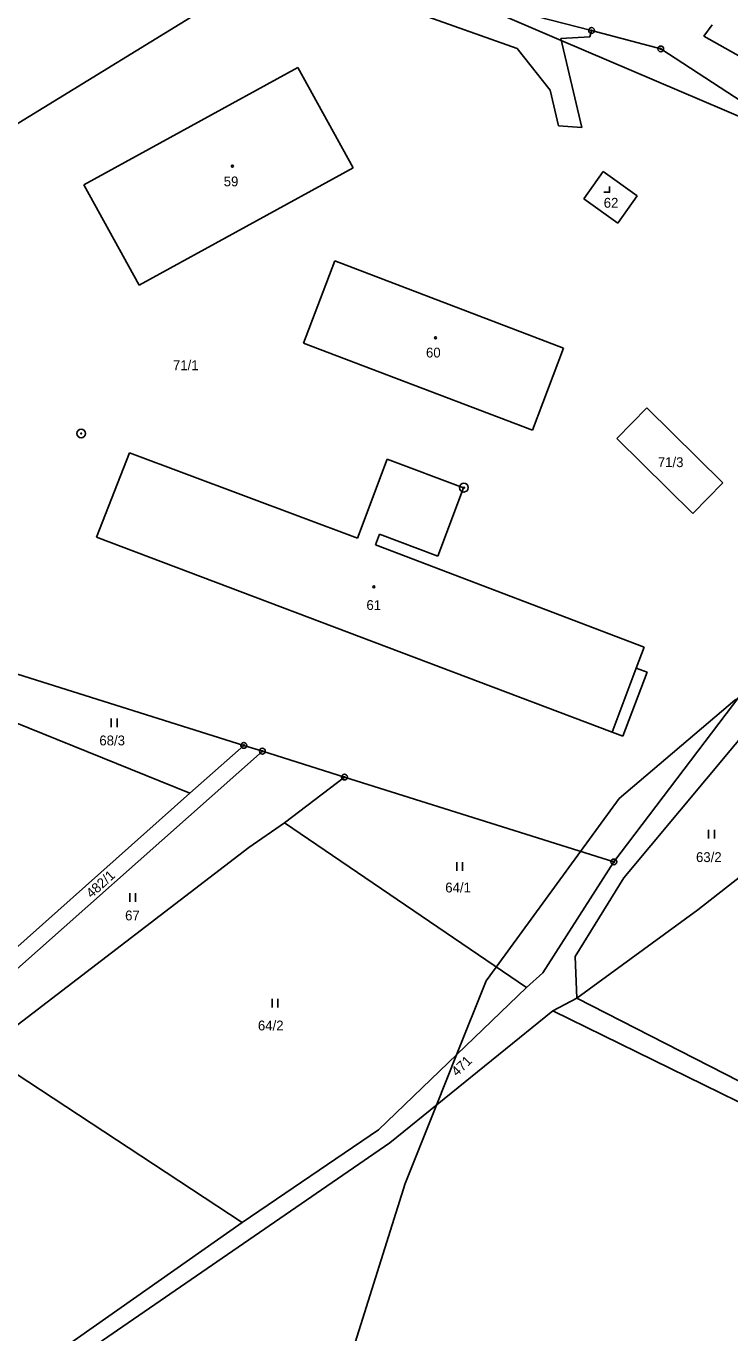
# Model space of a CAD drawing. Extents: x -547623 to -538651, y -1096714 to -1086522.
# Drawn here: x -543976.5 to -543854.9, y -1094596.8 to -1094371 of the extents above; entities that cross this region are included whole.
import ezdxf

# ---------------------------------------------------------------- set-up
doc = ezdxf.new("R2010")
doc.units = 0
for name, color, linetype in [('podzemní_provozovana', 7, 'Continuous'), ('Vrstva 1', 7, 'Continuous'), ('Vrstva 25', 7, 'Continuous'), ('Vrstva 33', 7, 'Continuous'), ('Vrstva 52', 7, 'Continuous'), ('Vrstva 83', 7, 'Continuous'), ('Vrstva 86', 7, 'Continuous'), ('Vrstva 90', 7, 'Continuous'), ('Vrstva 92', 7, 'Continuous')]:
    doc.layers.add(name, color=color, linetype=linetype)

msp = doc.modelspace()

# ---------------------------------------------------------------- linework, layer by layer
at = {"layer": 'Vrstva 1'}
for points in [[(-543930.3, -1094358.51), (-543878.77, -1094371.77)], [(-543934.68, -1094361.26), (-543986.14, -1094392.85)], [(-543911.59, -1094367.79), (-543891.65, -1094374.88)], [(-543879.1, -1094372.85), (-543878.77, -1094371.77)], [(-543878.77, -1094371.77), (-543866.82, -1094374.96)], [(-543859.39, -1094372.77), (-543857.96, -1094370.78)], [(-543829.89, -1094389.36), (-543859.39, -1094372.77)], [(-543891.65, -1094374.88), (-543885.92, -1094382.07)], [(-543884.09, -1094373.19), (-543879.1, -1094372.85)], [(-543880.43, -1094388.54), (-543884.09, -1094373.19)], [(-543866.82, -1094374.96), (-543852.74, -1094384.1)], [(-543929.5, -1094378.15), (-543966.48, -1094398.44)], [(-543919.98, -1094395.49), (-543929.5, -1094378.15)], [(-543885.92, -1094382.07), (-543884.46, -1094388.27)], [(-543884.46, -1094388.27), (-543880.43, -1094388.54)], [(-543956.96, -1094415.79), (-543919.98, -1094395.49)], [(-543876.76, -1094396.14), (-543880.13, -1094400.86)], [(-543870.87, -1094400.33), (-543876.76, -1094396.14)], [(-543966.48, -1094398.44), (-543956.96, -1094415.79)], [(-543880.13, -1094400.86), (-543874.24, -1094405.06)], [(-543870.87, -1094400.33), (-543874.24, -1094405.06)], [(-543923.11, -1094411.6), (-543928.54, -1094425.82)], [(-543883.6, -1094426.69), (-543923.11, -1094411.6)], [(-543928.54, -1094425.82), (-543888.96, -1094440.86)], [(-543888.96, -1094440.86), (-543883.6, -1094426.69)], [(-543874.4, -1094442.26), (-543869.21, -1094436.99)], [(-543869.21, -1094436.99), (-543856.08, -1094449.95)], [(-543861.26, -1094455.21), (-543874.4, -1094442.26)], [(-543964.33, -1094459.31), (-543958.59, -1094444.74)], [(-543958.59, -1094444.74), (-543919.22, -1094459.51)], [(-543914.09, -1094445.85), (-543919.22, -1094459.51)], [(-543914.09, -1094445.85), (-543900.9, -1094450.8)], [(-543900.9, -1094450.8), (-543905.32, -1094462.59)], [(-543856.08, -1094449.95), (-543861.26, -1094455.21)], [(-543875.21, -1094492.99), (-543964.33, -1094459.31)], [(-543916.13, -1094460.67), (-543915.43, -1094458.8)], [(-543869.66, -1094478.31), (-543916.13, -1094460.67)], [(-543915.43, -1094458.8), (-543905.32, -1094462.59)], [(-543871.04, -1094481.96), (-543869.66, -1094478.31)], [(-543977.99, -1094482.97), (-543938.86, -1094495.3)], [(-543873.39, -1094493.68), (-543869.17, -1094482.66)], [(-543869.17, -1094482.66), (-543871.04, -1094481.96)], [(-543874.92, -1094515.44), (-543853.17, -1094486.71)], [(-543986.26, -1094488.2), (-543948.16, -1094503.56)], [(-543873.21, -1094518.16), (-543849.31, -1094489.54)], [(-543873.39, -1094493.68), (-543875.21, -1094492.99)], [(-543935.66, -1094496.3), (-543987.34, -1094542.12)], [(-543948.16, -1094503.56), (-543938.86, -1094495.3)], [(-543938.86, -1094495.3), (-543935.66, -1094496.3)], [(-543935.66, -1094496.3), (-543921.46, -1094500.78)], [(-543931.84, -1094508.7), (-543921.46, -1094500.78)], [(-543921.46, -1094500.78), (-543874.92, -1094515.44)], [(-543989.1, -1094539.95), (-543948.16, -1094503.56)], [(-543860.39, -1094523.7), (-543837.63, -1094505.87)], [(-543938.01, -1094512.93), (-543931.84, -1094508.7)], [(-543931.84, -1094508.7), (-543890.01, -1094537.16)], [(-543983.04, -1094547.44), (-543938.01, -1094512.93)], [(-543887.17, -1094534.59), (-543874.92, -1094515.44)], [(-543881.62, -1094531.79), (-543873.21, -1094518.16)], [(-543881.31, -1094538.97), (-543860.39, -1094523.7)], [(-543881.31, -1094538.97), (-543881.62, -1094531.79)], [(-543890.01, -1094537.16), (-543887.17, -1094534.59)], [(-543915.6, -1094561.71), (-543890.01, -1094537.16)], [(-543885.48, -1094541.15), (-543881.31, -1094538.97)], [(-543837.95, -1094561.18), (-543881.31, -1094538.97)], [(-543913.61, -1094563.96), (-543885.48, -1094541.15)], [(-543885.48, -1094541.15), (-543842, -1094562.45)], [(-543939.12, -1094577.76), (-543980.55, -1094550.47)], [(-543939.12, -1094577.76), (-543915.6, -1094561.71)], [(-543982.35, -1094611.21), (-543913.61, -1094563.96)], [(-543983.7, -1094609), (-543939.12, -1094577.76)]]:
    msp.add_lwpolyline(points, dxfattribs=at)
at = {"layer": 'Vrstva 25'}
for p, q in [((-543961.77, -1094492.15), (-543961.77, -1094490.65)), ((-543960.77, -1094492.15), (-543960.77, -1094490.65)), ((-543858.55, -1094511.37), (-543858.55, -1094509.87)), ((-543857.55, -1094511.37), (-543857.55, -1094509.87)), ((-543902.07, -1094516.97), (-543902.07, -1094515.47)), ((-543901.07, -1094516.97), (-543901.07, -1094515.47)), ((-543958.55, -1094522.36), (-543958.55, -1094520.86)), ((-543957.55, -1094522.36), (-543957.55, -1094520.86)), ((-543933.97, -1094540.61), (-543933.97, -1094539.11)), ((-543932.97, -1094540.61), (-543932.97, -1094539.11))]:
    msp.add_line(p, q, dxfattribs=at)
msp.add_lwpolyline([(-543876.67, -1094399.73), (-543875.67, -1094399.73), (-543875.67, -1094398.73)], dxfattribs=at)
for centre in [(-543940.84, -1094395.22), (-543905.73, -1094424.87), (-543916.38, -1094467.92)]:
    msp.add_circle(centre, 0.175, dxfattribs=at)
at = {"layer": 'Vrstva 33'}
msp.add_lwpolyline([(-543871.04, -1094481.96), (-543875.21, -1094492.99)], dxfattribs=at)
at = {"layer": 'Vrstva 52'}
for points in [[(-543884.02, -1094373.48), (-543894.5, -1094369), (-543934.32, -1094361.04), (-543934.5, -1094361), (-543935.13, -1094360.95), (-543977.3, -1094357.3), (-543986.5, -1094356.5), (-544000.5, -1094363)], [(-543777, -1094440.5), (-543789.73, -1094425.6), (-543792.58, -1094422.26), (-543795.42, -1094418.93), (-543797.5, -1094416.5), (-543813.69, -1094406.78), (-543832.5, -1094395.5), (-543839.33, -1094392.58), (-543884.02, -1094373.48)], [(-543777, -1094440.5), (-543777.95, -1094441.08), (-543810.88, -1094461.18), (-543817.75, -1094465.37), (-543819.36, -1094466.35), (-543830.75, -1094473.31), (-543853.57, -1094487.24), (-543854, -1094487.5), (-543874, -1094504.5), (-543880.67, -1094513.63), (-543895.25, -1094533.6), (-543897, -1094536), (-543902.11, -1094548.76), (-543905.58, -1094557.45), (-543911, -1094571), (-543929.5, -1094630)]]:
    msp.add_lwpolyline(points, dxfattribs=at)
at = {"layer": 'Vrstva 83'}
for centre, radius in [((-543878.77, -1094371.77), 0.5), ((-543878.77, -1094371.77), 0.1), ((-543866.82, -1094374.96), 0.5), ((-543866.82, -1094374.96), 0.1), ((-543966.95, -1094441.42), 0.75), ((-543966.95, -1094441.42), 0.1), ((-543900.82, -1094450.77), 0.75), ((-543900.82, -1094450.77), 0.1), ((-543938.86, -1094495.3), 0.5), ((-543938.86, -1094495.3), 0.1), ((-543935.66, -1094496.3), 0.5), ((-543935.66, -1094496.3), 0.1), ((-543921.46, -1094500.78), 0.5), ((-543921.46, -1094500.78), 0.1), ((-543874.92, -1094515.44), 0.5), ((-543874.92, -1094515.44), 0.1)]:
    msp.add_circle(centre, radius, dxfattribs=at)
at = {"layer": 'Vrstva 90'}
for points in [[(-543929.5, -1094378.15), (-543966.48, -1094398.44)], [(-543919.98, -1094395.49), (-543929.5, -1094378.15)], [(-543956.96, -1094415.79), (-543919.98, -1094395.49)], [(-543966.48, -1094398.44), (-543956.96, -1094415.79)], [(-543923.11, -1094411.6), (-543928.54, -1094425.82)], [(-543883.6, -1094426.69), (-543923.11, -1094411.6)], [(-543928.54, -1094425.82), (-543888.96, -1094440.86)], [(-543888.96, -1094440.86), (-543883.6, -1094426.69)], [(-543964.33, -1094459.31), (-543958.59, -1094444.74)], [(-543958.59, -1094444.74), (-543919.22, -1094459.51)], [(-543914.09, -1094445.85), (-543919.22, -1094459.51)], [(-543914.09, -1094445.85), (-543900.9, -1094450.8)], [(-543900.9, -1094450.8), (-543905.32, -1094462.59)], [(-543875.21, -1094492.99), (-543964.33, -1094459.31)], [(-543916.13, -1094460.67), (-543915.43, -1094458.8)], [(-543869.66, -1094478.31), (-543916.13, -1094460.67)], [(-543915.43, -1094458.8), (-543905.32, -1094462.59)], [(-543871.04, -1094481.96), (-543869.66, -1094478.31)], [(-543871.04, -1094481.96), (-543875.21, -1094492.99)]]:
    msp.add_lwpolyline(points, dxfattribs=at)

# ---------------------------------------------------------------- texts
at = {"layer": 'podzemní_provozovana'}
msp.add_text('471', height=1.7, rotation=43.886, dxfattribs=at).set_placement((-543902.02, -1094552.61))
at = {"layer": 'Vrstva 86'}
for s, p in [('71/1', (-543951.11, -1094430.47)), ('71/3', (-543867.32, -1094447.22)), ('68/3', (-543963.82, -1094495.3)), ('63/2', (-543860.72, -1094515.46)), ('64/1', (-543904.05, -1094520.71)), ('67', (-543959.37, -1094525.54)), ('64/2', (-543936.42, -1094544.55))]:
    msp.add_text(s, height=1.7, dxfattribs=at).set_placement(p)
msp.add_text('482/1', height=1.7, rotation=42.2951, dxfattribs=at).set_placement((-543965.17, -1094521.8))
at = {"layer": 'Vrstva 92'}
for s, p in [('59', (-543942.33, -1094398.71)), ('62', (-543876.67, -1094402.4)), ('60', (-543907.38, -1094428.28)), ('61', (-543917.67, -1094471.91))]:
    msp.add_text(s, height=1.7, dxfattribs=at).set_placement(p)

doc.saveas('drawing.dxf')
